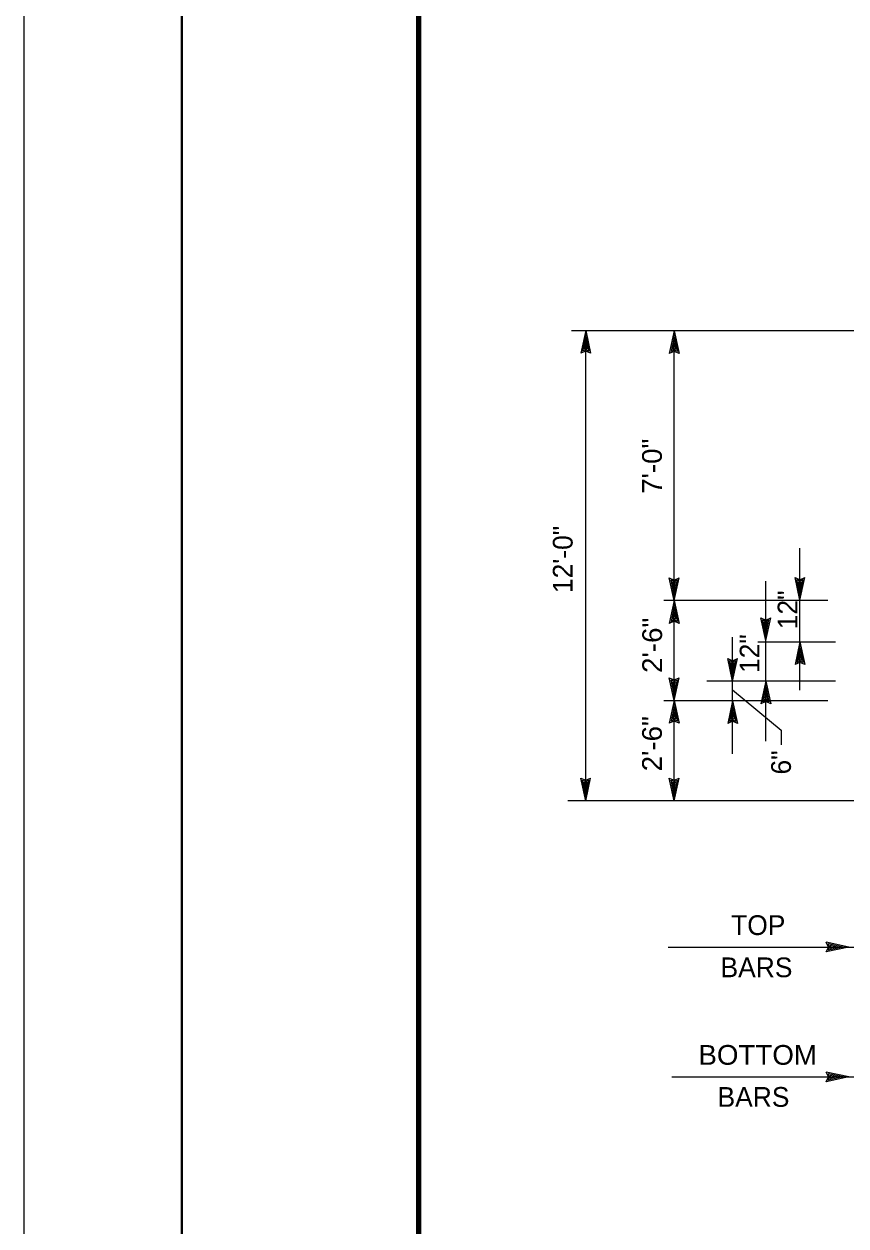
# Model space of a CAD drawing. Extents: x -22.3 to 19.7, y -11.8 to 18.2.
# Drawn here: x -22.31 to -17.11, y -1.06 to 6.54 of the extents above; entities that cross this region are included whole.
import ezdxf
from ezdxf.enums import TextEntityAlignment as Align

# ---------------------------------------------------------------- set-up
doc = ezdxf.new("R2010")
doc.units = 0
doc.header["$LTSCALE"] = 0.05
doc.layers.add('1', color=7, linetype='Continuous', lineweight=13)

msp = doc.modelspace()

# ---------------------------------------------------------------- linework, layer by layer
at = {"layer": '1'}
for p, q in [((-22.30942, -11.83969), (-22.30942, 18.16031)), ((-8.91642, 4.60131), (-18.84342, 4.60131)), ((-18.75342, 4.60331), (-18.78442, 4.45931)), ((-18.75342, 4.56631), (-18.77342, 4.47231)), ((-18.75342, 1.62731), (-18.75342, 4.60331)), ((-18.75342, 4.60331), (-18.72242, 4.45931)), ((-18.75342, 4.56631), (-18.73342, 4.47231)), ((-18.19342, 4.60131), (-18.22442, 4.45731)), ((-18.19342, 4.56431), (-18.21342, 4.47031)), ((-18.19342, 4.60131), (-18.16242, 4.45731)), ((-18.19342, 4.56431), (-18.17342, 4.47031)), ((-18.75342, 4.53031), (-18.76242, 4.48531)), ((-18.75342, 4.48931), (-18.76242, 4.48531)), ((-18.75342, 4.53031), (-18.74342, 4.48531)), ((-18.74342, 4.48531), (-18.75342, 4.48931)), ((-18.19342, 4.52831), (-18.20242, 4.48331)), ((-18.19342, 4.52831), (-18.18342, 4.48331)), ((-18.75342, 4.48131), (-18.77342, 4.47231)), ((-18.73342, 4.47231), (-18.75342, 4.48131)), ((-18.19342, 4.47931), (-18.21342, 4.47031)), ((-18.19342, 4.48731), (-18.20242, 4.48331)), ((-18.18342, 4.48331), (-18.19342, 4.48731)), ((-18.17342, 4.47031), (-18.19342, 4.47931)), ((-18.19342, 2.89431), (-18.22442, 3.03831)), ((-18.19342, 2.93131), (-18.21342, 3.02531)), ((-18.21342, 3.02531), (-18.19342, 3.01631)), ((-18.19342, 2.96731), (-18.20342, 3.01231)), ((-18.20342, 3.01231), (-18.19342, 3.00831)), ((-18.19342, 2.89431), (-18.16242, 3.03831)), ((-18.19342, 2.93131), (-18.17342, 3.02531)), ((-18.19342, 3.01631), (-18.17342, 3.02531)), ((-18.19342, 2.96731), (-18.18442, 3.01231)), ((-18.19342, 3.00831), (-18.18442, 3.01231)), ((-17.39742, 2.89631), (-17.42842, 3.04031)), ((-17.39742, 2.93331), (-17.41742, 3.02731)), ((-17.41742, 3.02731), (-17.39742, 3.01831)), ((-17.39742, 2.96931), (-17.40742, 3.01431)), ((-17.40742, 3.01431), (-17.39742, 3.01031)), ((-17.39742, 2.89631), (-17.36642, 3.04031)), ((-17.39742, 2.93331), (-17.37742, 3.02731)), ((-17.39742, 3.01831), (-17.37742, 3.02731)), ((-17.39742, 2.96931), (-17.38842, 3.01431)), ((-17.39742, 3.01031), (-17.38842, 3.01431)), ((-17.22042, 2.89431), (-18.25942, 2.89431)), ((-18.19342, 2.89431), (-18.22442, 2.75031)), ((-18.19342, 2.89431), (-18.16242, 2.75031)), ((-18.19342, 2.85731), (-18.21342, 2.76331)), ((-18.19342, 2.82131), (-18.20242, 2.77631)), ((-18.19342, 2.85731), (-18.17342, 2.76331)), ((-18.19342, 2.82131), (-18.18342, 2.77631)), ((-18.19342, 2.77231), (-18.21342, 2.76331)), ((-18.19342, 2.78031), (-18.20242, 2.77631)), ((-18.18342, 2.77631), (-18.19342, 2.78031)), ((-18.17342, 2.76331), (-18.19342, 2.77231)), ((-17.61342, 2.64131), (-17.64442, 2.78531)), ((-17.61342, 2.67831), (-17.63342, 2.77231)), ((-17.63342, 2.77231), (-17.61342, 2.76331)), ((-17.61342, 2.71431), (-17.62342, 2.75931)), ((-17.62342, 2.75931), (-17.61342, 2.75531)), ((-17.61342, 2.64131), (-17.58242, 2.78531)), ((-17.61342, 2.67831), (-17.59342, 2.77231)), ((-17.61342, 2.76331), (-17.59342, 2.77231)), ((-17.61342, 2.71431), (-17.60442, 2.75931)), ((-17.61342, 2.75531), (-17.60442, 2.75931)), ((-17.17142, 2.63231), (-17.66442, 2.63231)), ((-17.39742, 2.63331), (-17.42842, 2.48931)), ((-17.39742, 2.59631), (-17.41742, 2.50231)), ((-17.39742, 2.63331), (-17.36642, 2.48931)), ((-17.39742, 2.59631), (-17.37742, 2.50231)), ((-17.82342, 2.38431), (-17.85442, 2.52831)), ((-17.82342, 2.42131), (-17.84342, 2.51531)), ((-17.84342, 2.51531), (-17.82342, 2.50631)), ((-17.82342, 2.38431), (-17.79242, 2.52831)), ((-17.82342, 2.42131), (-17.80342, 2.51531)), ((-17.82342, 2.50631), (-17.80342, 2.51531)), ((-17.39742, 2.51131), (-17.41742, 2.50231)), ((-17.39742, 2.56031), (-17.40642, 2.51531)), ((-17.39742, 2.51931), (-17.40642, 2.51531)), ((-17.39742, 2.56031), (-17.38742, 2.51531)), ((-17.38742, 2.51531), (-17.39742, 2.51931)), ((-17.37742, 2.50231), (-17.39742, 2.51131)), ((-17.82342, 2.45731), (-17.83342, 2.50231)), ((-17.83342, 2.50231), (-17.82342, 2.49831)), ((-17.82342, 2.45731), (-17.81442, 2.50231)), ((-17.82342, 2.49831), (-17.81442, 2.50231)), ((-18.19342, 2.26231), (-18.22442, 2.40631)), ((-18.19342, 2.29931), (-18.21342, 2.39331)), ((-18.21342, 2.39331), (-18.19342, 2.38431)), ((-18.19342, 2.33531), (-18.20342, 2.38031)), ((-18.20342, 2.38031), (-18.19342, 2.37631)), ((-18.19342, 2.26231), (-18.16242, 2.40631)), ((-18.19342, 2.29931), (-18.17342, 2.39331)), ((-18.19342, 2.38431), (-18.17342, 2.39331)), ((-18.19342, 2.33531), (-18.18442, 2.38031)), ((-18.19342, 2.37631), (-18.18442, 2.38031)), ((-17.17142, 2.38431), (-17.98642, 2.38431)), ((-17.61342, 2.38531), (-17.64442, 2.24131)), ((-17.61342, 2.38531), (-17.58242, 2.24131)), ((-17.61342, 2.34831), (-17.63342, 2.25431)), ((-17.61342, 2.31231), (-17.62242, 2.26731)), ((-17.61342, 2.34831), (-17.59342, 2.25431)), ((-17.61342, 2.31231), (-17.60342, 2.26731)), ((-17.22042, 2.26031), (-18.25942, 2.26031)), ((-18.19342, 2.26231), (-18.22442, 2.11831)), ((-18.19342, 2.22531), (-18.21342, 2.13131)), ((-18.19342, 2.26231), (-18.16242, 2.11831)), ((-18.19342, 2.22531), (-18.17342, 2.13131)), ((-17.82342, 2.26131), (-17.85442, 2.11731)), ((-17.82342, 2.22431), (-17.84342, 2.13031)), ((-17.82342, 2.26131), (-17.79242, 2.11731)), ((-17.82342, 2.22431), (-17.80342, 2.13031)), ((-17.61342, 2.26331), (-17.63342, 2.25431)), ((-17.61342, 2.27131), (-17.62242, 2.26731)), ((-17.60342, 2.26731), (-17.61342, 2.27131)), ((-17.59342, 2.25431), (-17.61342, 2.26331)), ((-18.19342, 2.14031), (-18.21342, 2.13131)), ((-18.19342, 2.18931), (-18.20242, 2.14431)), ((-18.19342, 2.14831), (-18.20242, 2.14431)), ((-18.19342, 2.18931), (-18.18342, 2.14431)), ((-18.18342, 2.14431), (-18.19342, 2.14831)), ((-18.17342, 2.13131), (-18.19342, 2.14031)), ((-17.82342, 2.13931), (-17.84342, 2.13031)), ((-17.82342, 2.18831), (-17.83242, 2.14331)), ((-17.82342, 2.14731), (-17.83242, 2.14331)), ((-17.82342, 2.18831), (-17.81342, 2.14331)), ((-17.81342, 2.14331), (-17.82342, 2.14731)), ((-17.80342, 2.13031), (-17.82342, 2.13931)), ((-18.75342, 1.62731), (-18.78442, 1.77131)), ((-18.75342, 1.66431), (-18.77342, 1.75831)), ((-18.77342, 1.75831), (-18.75342, 1.74931)), ((-18.75342, 1.62731), (-18.72242, 1.77131)), ((-18.75342, 1.66431), (-18.73342, 1.75831)), ((-18.75342, 1.74931), (-18.73342, 1.75831)), ((-18.19342, 1.62731), (-18.22442, 1.77131)), ((-18.19342, 1.66431), (-18.21342, 1.75831)), ((-18.21342, 1.75831), (-18.19342, 1.74931)), ((-18.19342, 1.62731), (-18.16242, 1.77131)), ((-18.19342, 1.66431), (-18.17342, 1.75831)), ((-18.19342, 1.74931), (-18.17342, 1.75831)), ((-18.75342, 1.70031), (-18.76342, 1.74531)), ((-18.76342, 1.74531), (-18.75342, 1.74131)), ((-18.75342, 1.70031), (-18.74442, 1.74531)), ((-18.75342, 1.74131), (-18.74442, 1.74531)), ((-18.19342, 1.70031), (-18.20342, 1.74531)), ((-18.20342, 1.74531), (-18.19342, 1.74131)), ((-18.19342, 1.70031), (-18.18442, 1.74531)), ((-18.19342, 1.74131), (-18.18442, 1.74531)), ((-8.91642, 1.62731), (-18.86742, 1.62731)), ((-17.08742, 0.70231), (-17.23142, 0.73331)), ((-17.08742, 0.70231), (-17.23142, 0.67131)), ((-17.12442, 0.70231), (-17.21842, 0.72231)), ((-17.20942, 0.70231), (-17.21842, 0.72231)), ((-17.12442, 0.70231), (-17.21842, 0.68231)), ((-17.21842, 0.68231), (-17.20942, 0.70231)), ((-17.16042, 0.70231), (-17.20542, 0.71131)), ((-17.20142, 0.70231), (-17.20542, 0.71131)), ((-17.16042, 0.70231), (-17.20542, 0.69231)), ((-17.20542, 0.69231), (-17.20142, 0.70231)), ((-17.08742, -0.11969), (-17.23142, -0.08869)), ((-17.08742, -0.11969), (-17.23142, -0.15069)), ((-17.12442, -0.11969), (-17.21842, -0.09969)), ((-17.20942, -0.11969), (-17.21842, -0.09969)), ((-17.12442, -0.11969), (-17.21842, -0.13969)), ((-17.21842, -0.13969), (-17.20942, -0.11969)), ((-17.16042, -0.11969), (-17.20542, -0.11069)), ((-17.20142, -0.11969), (-17.20542, -0.11069)), ((-17.16042, -0.11969), (-17.20542, -0.12969)), ((-17.20542, -0.12969), (-17.20142, -0.11969))]:
    msp.add_line(p, q, dxfattribs=at)
at = {"layer": '1', "lineweight": 40}
msp.add_lwpolyline([(-21.30942, -10.83969), (-21.30942, 17.16031), (18.69058, 17.16031), (18.69058, -10.83969)], close=True, dxfattribs=at)
at = {"layer": '1', "lineweight": 90}
msp.add_lwpolyline([(-19.80942, 16.66031), (18.19058, 16.66031), (18.19058, -10.33969), (-19.80942, -10.33969)], close=True, dxfattribs=at)
at = {"layer": '1'}
for points in [[(-18.19342, 1.62731), (-18.19342, 2.26231), (-18.19342, 2.89431), (-18.19342, 4.60131)], [(-18.72242, 4.45931), (-18.75342, 4.47331), (-18.78442, 4.45931)], [(-18.16242, 4.45731), (-18.19342, 4.47131), (-18.22442, 4.45731)], [(-17.39742, 2.32831), (-17.39742, 2.63331), (-17.39742, 2.89631), (-17.39742, 3.22631)], [(-18.22442, 3.03831), (-18.19342, 3.02431), (-18.16242, 3.03831)], [(-17.61342, 2.00431), (-17.61342, 2.38531), (-17.61342, 2.64131), (-17.61342, 3.01731)], [(-17.42842, 3.04031), (-17.39742, 3.02631), (-17.36642, 3.04031)], [(-18.16242, 2.75031), (-18.19342, 2.76431), (-18.22442, 2.75031)], [(-17.64442, 2.78531), (-17.61342, 2.77131), (-17.58242, 2.78531)], [(-17.82342, 1.92531), (-17.82342, 2.26131), (-17.82342, 2.38431), (-17.82342, 2.66331)], [(-17.85442, 2.52831), (-17.82342, 2.51431), (-17.79242, 2.52831)], [(-17.36642, 2.48931), (-17.39742, 2.50331), (-17.42842, 2.48931)], [(-18.22442, 2.40631), (-18.19342, 2.39231), (-18.16242, 2.40631)], [(-17.82342, 2.32931), (-17.51642, 2.07431), (-17.51642, 1.98131)], [(-17.58242, 2.24131), (-17.61342, 2.25531), (-17.64442, 2.24131)], [(-18.16242, 2.11831), (-18.19342, 2.13231), (-18.22442, 2.11831)], [(-17.79242, 2.11731), (-17.82342, 2.13131), (-17.85442, 2.11731)], [(-18.78442, 1.77131), (-18.75342, 1.75731), (-18.72242, 1.77131)], [(-18.22442, 1.77131), (-18.19342, 1.75731), (-18.16242, 1.77131)], [(-18.23142, 0.70231), (-17.08742, 0.70231), (-16.99942, 0.70231), (-13.87442, 0.70231), (-13.61742, 0.70231), (-12.88542, 0.70231), (-12.61242, 0.70231), (-11.61942, 0.70231), (-11.37642, 0.70231), (-10.61342, 0.70231), (-10.35942, 0.70231), (-9.37342, 0.70231), (-9.22442, 0.70231), (-8.48642, 0.70231), (-8.41442, 0.70231), (-7.89942, 0.70231)], [(-17.23142, 0.67131), (-17.21742, 0.70231), (-17.23142, 0.73331)], [(-18.20842, -0.11969), (-17.08742, -0.11969), (-16.99942, -0.11969), (-9.35942, -0.11969), (-9.22942, -0.11969), (-8.48642, -0.11969), (-8.42042, -0.11969), (-7.80142, -0.11969)], [(-17.23142, -0.15069), (-17.21742, -0.11969), (-17.23142, -0.08869)]]:
    msp.add_lwpolyline(points, dxfattribs=at)

# ---------------------------------------------------------------- texts
at = {"layer": '1', "width": 1.05}
for s, p in [('7\'-0"', (-18.27142, 3.74481)), ('2\'-6"', (-18.27042, 2.61181)), ('2\'-6"', (-18.27142, 1.98881))]:
    msp.add_text(s, height=0.125, rotation=90, dxfattribs=at).set_placement(p, align=Align.CENTER)
at = {"layer": '1'}
msp.add_text('12\'-0"', height=0.125, rotation=90, dxfattribs=at).set_placement((-18.83642, 3.15481), align=Align.CENTER)
for p in [(-17.41342, 2.71331), (-17.65342, 2.43631)]:
    msp.add_text('12"', height=0.125, rotation=90, dxfattribs=at).set_placement(p)
msp.add_text('6"', height=0.125, rotation=90, dxfattribs=at).set_placement((-17.45442, 1.94631), align=Align.RIGHT)
msp.add_text('TOP', height=0.125, dxfattribs=at).set_placement((-17.48942, 0.77831), align=Align.RIGHT)
for p in [(-17.67242, 0.51131), (-17.69142, -0.30869)]:
    msp.add_text('BARS', height=0.125, dxfattribs=at).set_placement(p, align=Align.CENTER)
at = {"layer": '1', "width": 1.05}
msp.add_text('BOTTOM', height=0.125, dxfattribs=at).set_placement((-17.28942, -0.04269), align=Align.RIGHT)

doc.saveas('drawing.dxf')
